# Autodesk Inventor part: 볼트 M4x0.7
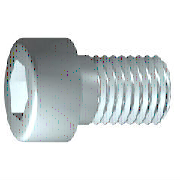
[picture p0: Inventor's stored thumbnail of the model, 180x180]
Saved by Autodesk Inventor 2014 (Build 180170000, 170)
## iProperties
IsCustomPart: 0
Created: 2015-12
Part Number: 볼트 M4x0.7
Material: 강철, 연강
Description: 6각머리 태핑 나사
Document SubType Name: Modeling
Standard: KS B 1003
Designer: mdu
Standards Organization: KS
Language: ko-KR
Size Designation: M 4 x 12
Categories: <MemberInstance><Categories><Category DisplayName="조임쇠" InternalName="e4da775c-781d-43d5-af7c-5136215cf5a6" Mnemonic="FSTN"><Category DisplayName="볼트" InternalN
Density: 1 g/cm^3
Appearance: 강철
Author: mdu
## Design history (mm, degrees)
sketch "스케치1"
  geometry: L1 (-1, 0)-(12, 0); L2 (12, 0)-(12, 2); L3 (12, 2)-(1.75, 2); L4 (1.75, 2)-(1.32, 2); L5 (1.32, 2)-(0, 2); L6 (0, 2)-(0, 3.5); L7 (0, 3.5)-(-4, 3.5); L8 (-4, 3.5)-(-4, 1.732); L9 (-4, 1.732)-(-2, 1.732); L10 (-2, 1.732)-(-1, 0); L11 (-7.2, 0)-(15.2, 0) reference; L12 (0, -0.7)-(0, 4.2) reference; L13 (1.75, 2)-(0, 2)
  constraints: 22 end point, 6 parallel, 2 collinear, 2 perpendicular, 1 horizontal, 1 point on line
  dimensions: "d1" = 10.25 distance from line of L3.end L2 (= GEL); "d2" = 0.42952 distance of L4.end L3.end (computed from GAL); "d3" = 4 distance between parallel lines of L8 L6 (= KOH); "d4" = 2 distance of L8.end L9.end (= INTI); "d5" = 60 deg angle of L10 L1; "d6" = 4 diameter of L3 L1 (= GD); "d7" = 4 diameter of L5 L1 (= BDM); "d8" = 3.4641 diameter of L9 L1 (= 1.1547 x SW); "d9" = 7 diameter of L7 L1 (= KOD); "d26" = 12 distance between parallel lines of L12 L2 (= NLG)
revolve "본체" sketch "스케치1" stored, may be unused: angle "d10" = 90 deg
sketch "스케치2"
  geometry: L1 (0, -4.9)-(0, 4.9) reference; L2 (-4.9, 0)-(4.9, 0) reference; L3 (1.732, 0)-(0.866, -1.5); L4 (0.866, -1.5)-(-0.866, -1.5); L5 (-0.866, -1.5)-(-1.732, 0); L6 (-1.732, 0)-(-0.866, 1.5); L7 (-0.866, 1.5)-(0.866, 1.5); L8 (0.866, 1.5)-(1.732, 0); 2 further points
  constraints: 12 end point, 1 coincident, 1 horizontal alignment, 1 point on line, 12 other
extrude "슬롯" join sketch "스케치2" stored distance "d11" = 10; taper "d12" = 0 deg
workplane "Work Plane1"
fillet "Fillet2" dims "d30" = 0.1 (= R)
body "Solid1"
fillet "모깎기1" dims "d17" = 0.4 (= RR)
feature "스레드" dims "d13" = 10.25 (= GEL), "d14" = 0
chamfer "모따기1" distance "d15" = 0.42941 (= -0.5 x SPD + 0.5 x GD); stored, may be unused: second distance "d16" = 0.42941 (= GUL), angle "d27" = 45 deg
other parameters: "GD" = 4 (= NND) [user parameter; used in 2 equation terms], "NLG" = 12 [user parameter; used in 1 equation term], "GEL" = 10.25 [user parameter; used in 2 equation terms], "KOD" = 7 [user parameter; used in 1 equation term], "KOH" = 4 [user parameter; used in 1 equation term], "INTI" = 2 [user parameter; used in 1 equation term], "GAL" = 0.42941 (= 0.61345 x PTC) [user parameter; used in 1 equation term], "GUL" = 0.42941 (= 0.61345 x PTC) [user parameter; used in 1 equation term], "BDM" = 4 (= NND) [user parameter; used in 1 equation term], "SW" = 3 [user parameter; used in 2 equation terms], "RR" = 0.4 [user parameter; used in 1 equation term], "SPD" = 3.14117 (= NND - 1.2269 x PTC) [user parameter; used in 1 equation term], "d19" = 0, "d28" = 0, "d29" = 0, "R" = 0.1 [user parameter; used in 1 equation term], "PHH" = 0.2 [user parameter], "GD1" = 3.14117 (= THREADDIA - 1.2269 x PTC) [user parameter], "THREADDIA" = 4 [user parameter; used in 1 equation term], "FAWI" = 45 deg [user parameter], "TPU" = 14.28571 (computed from PTC) [user parameter], "PTC" = 0.7 [user parameter; used in 5 equation terms], "NND" = 4 [user parameter; used in 3 equation terms], "TOA" = 30 deg [user parameter], "E0" = 3.465 (= 1.155 x SW) [user parameter]
